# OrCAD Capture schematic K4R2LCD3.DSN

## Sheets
1 P3: Microtech 320x240 3.5": size Custom; title: K4 Microtech 3.5 adapter; rev: 1.0; note: K4R2-LCD
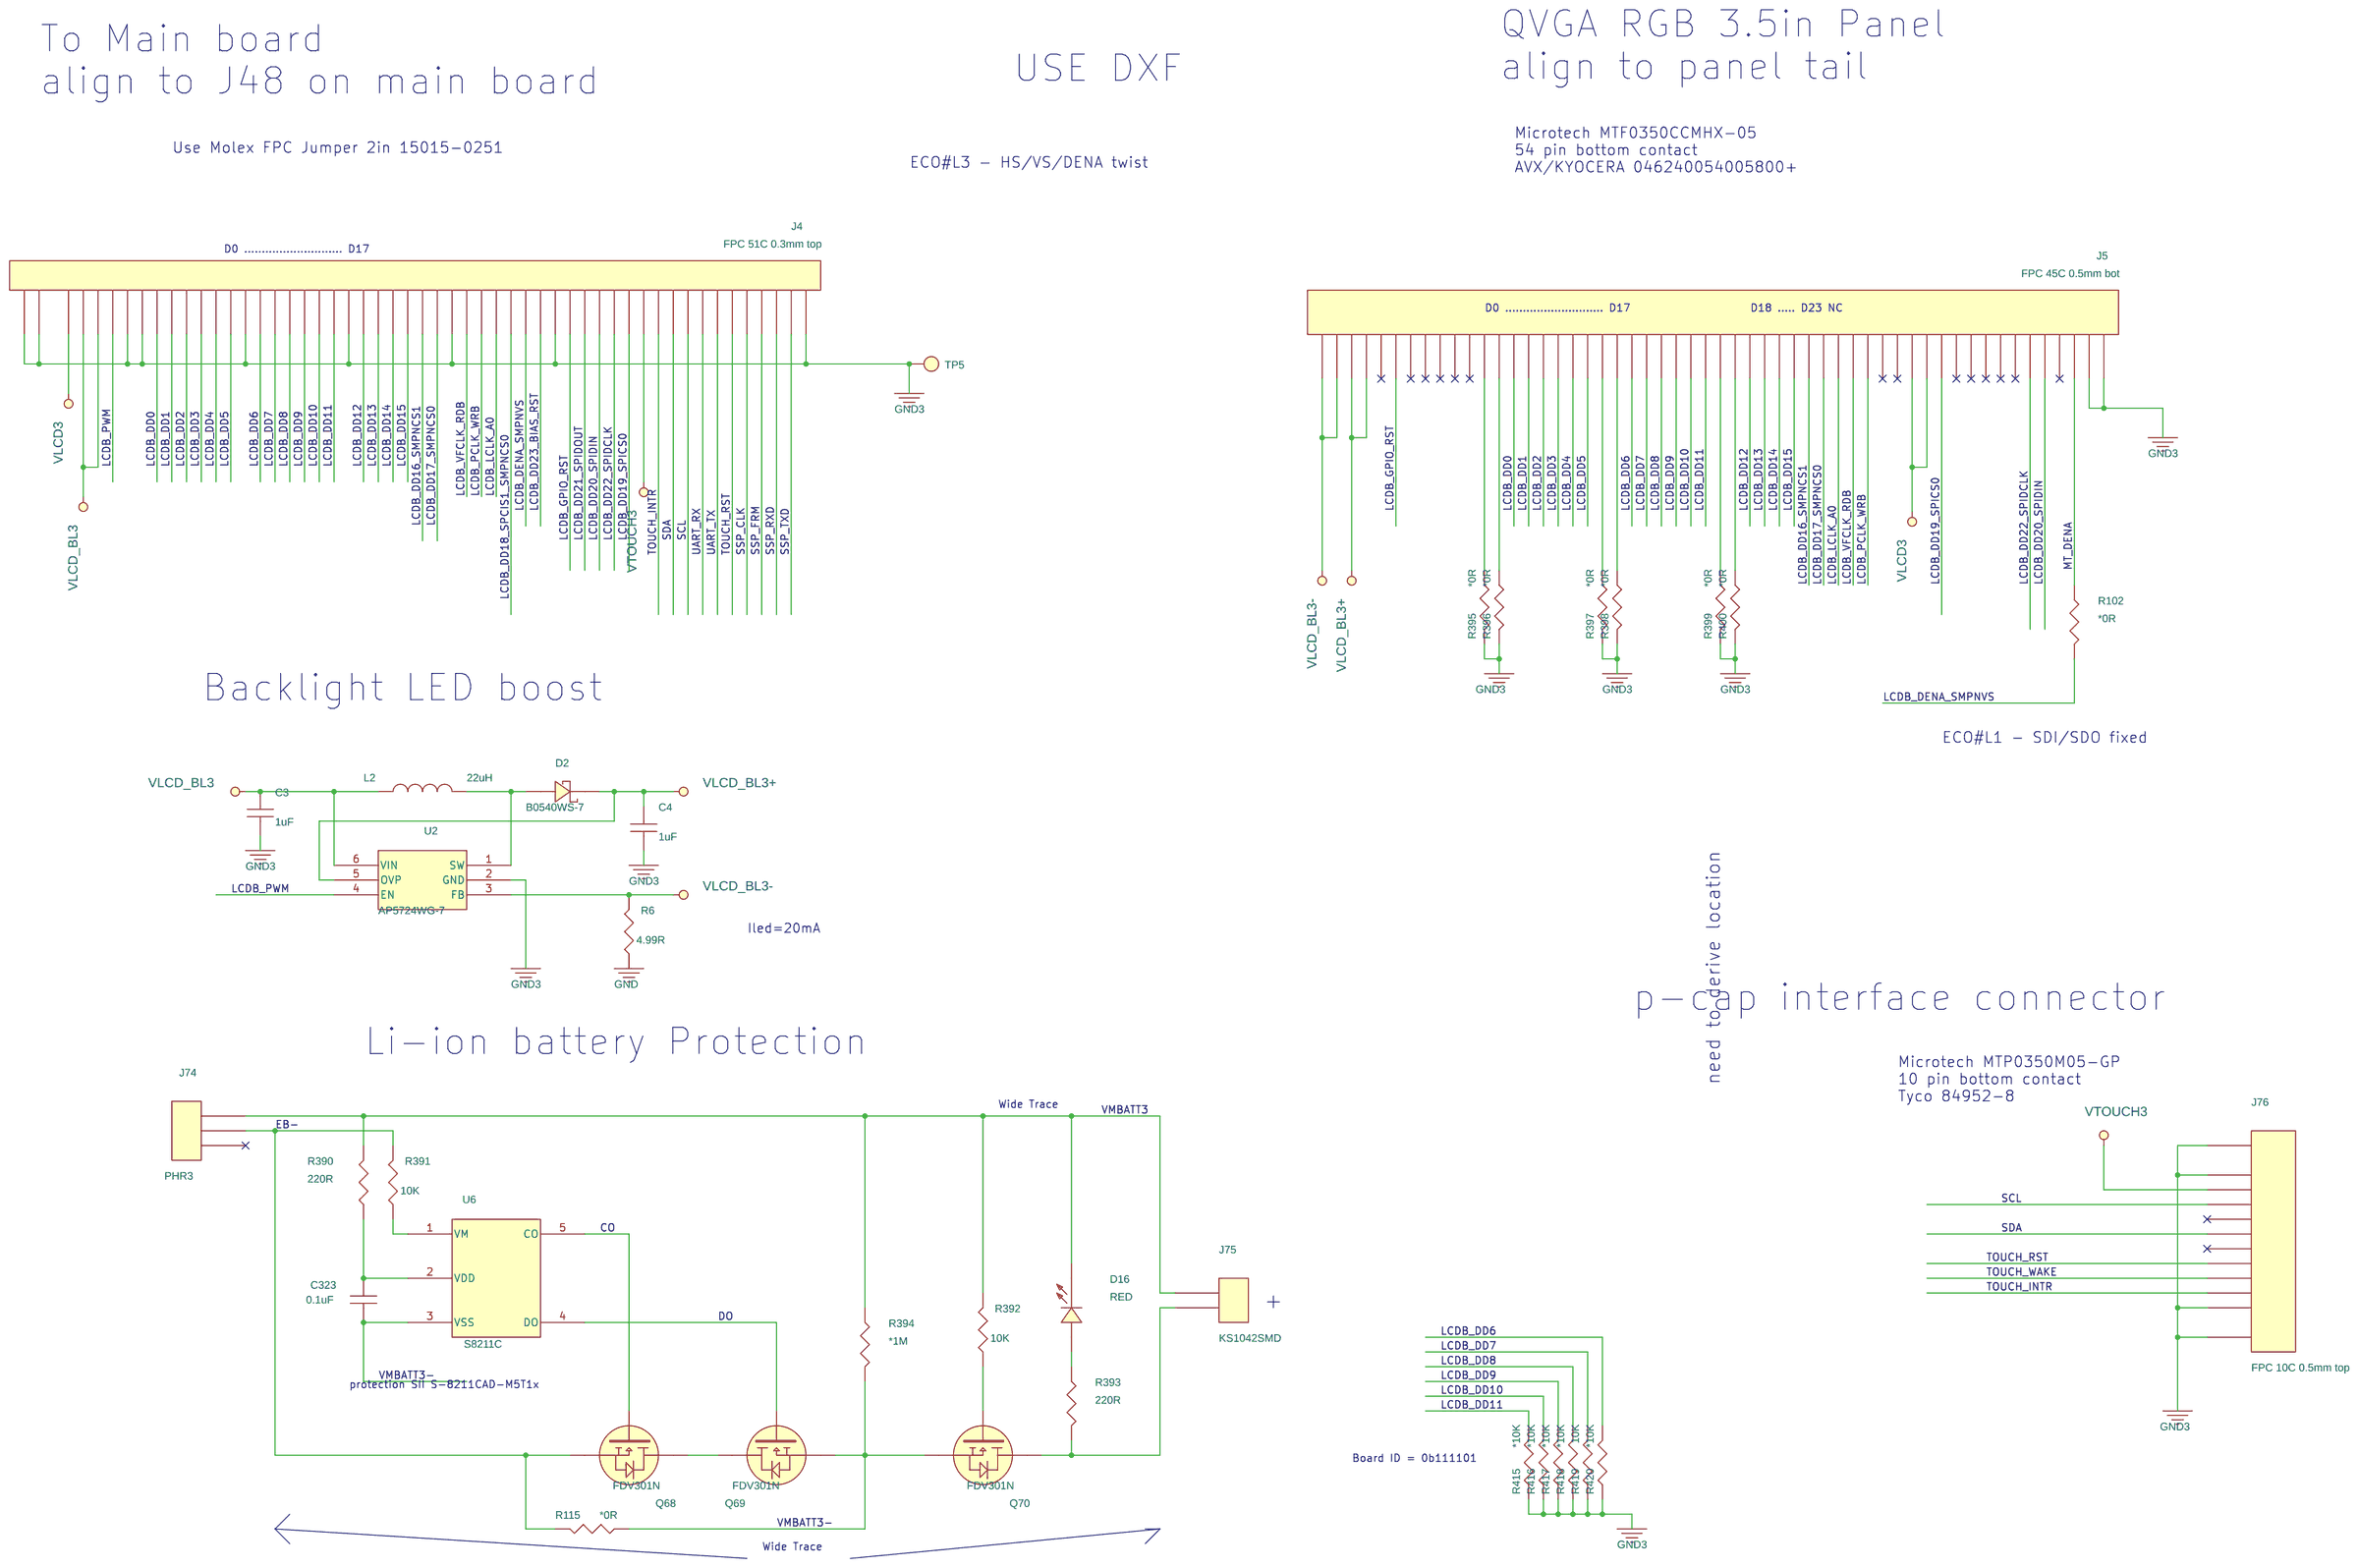
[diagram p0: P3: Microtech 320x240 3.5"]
2 P1: Title block: title: K4 LCD bridge
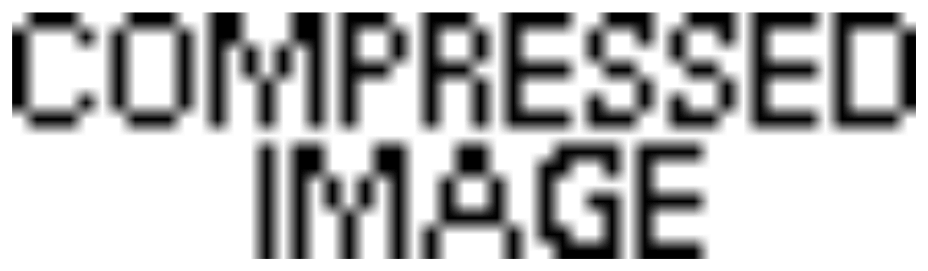
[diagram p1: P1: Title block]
3 P9: reconfigurable adapter: size Custom; title: K4 Configurable adapter
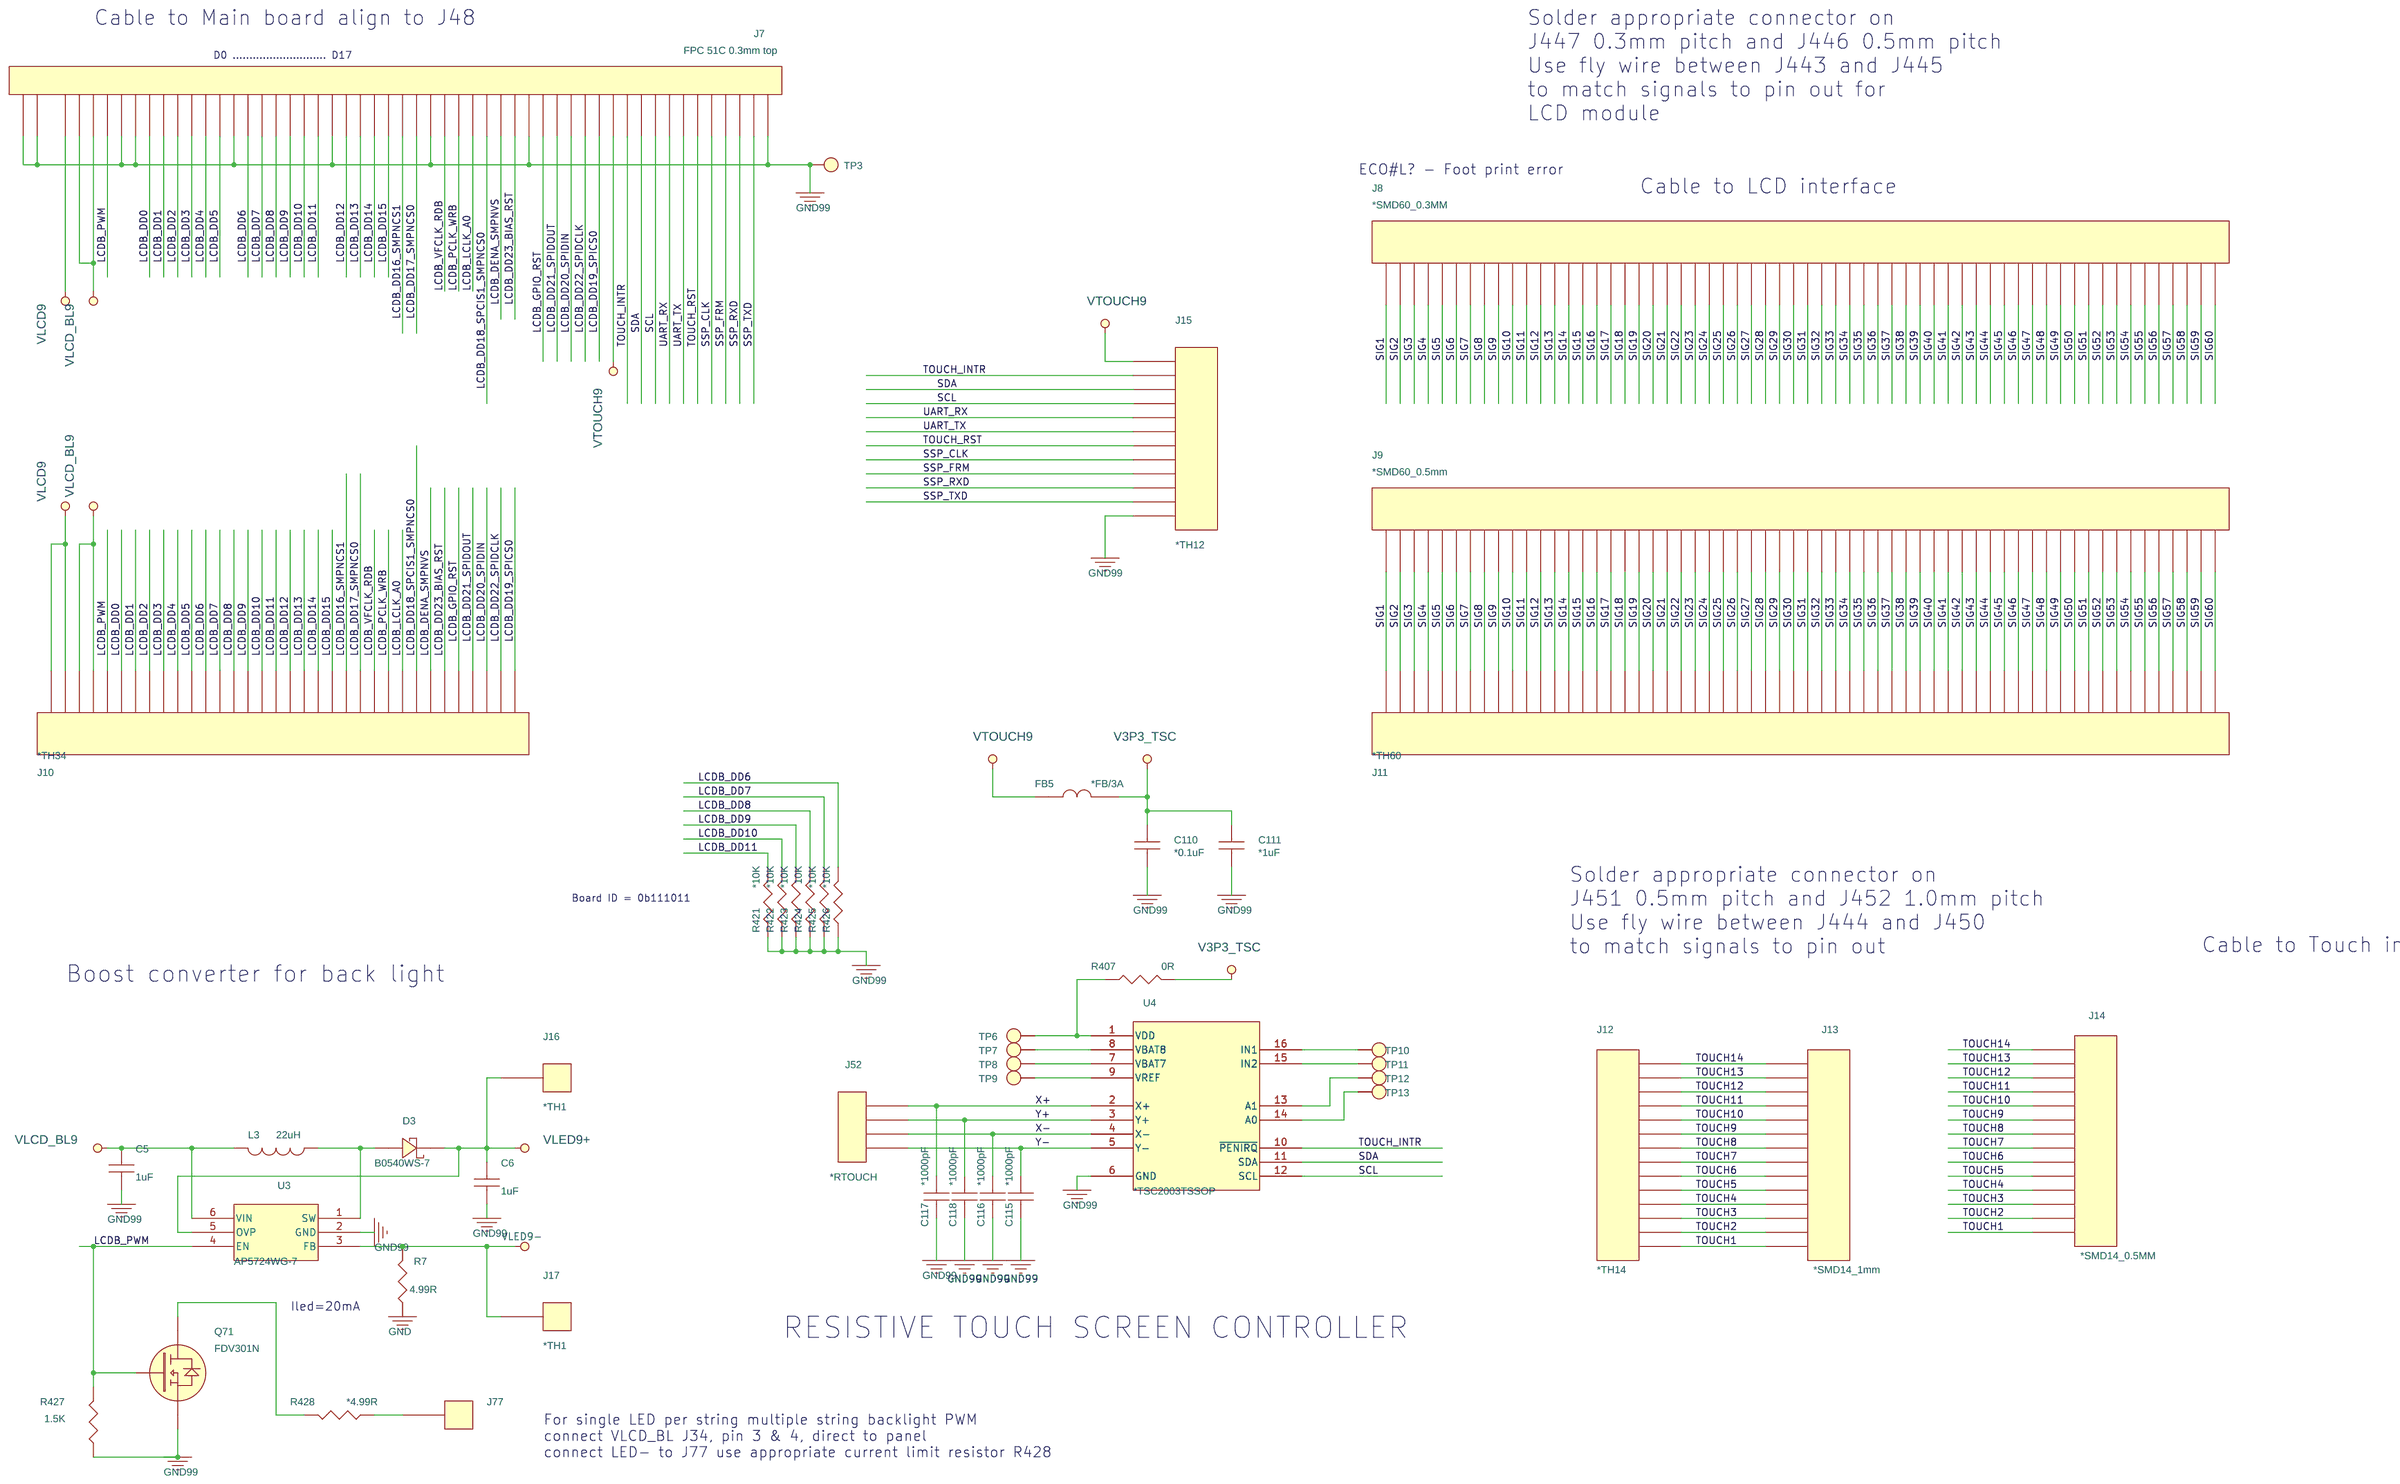
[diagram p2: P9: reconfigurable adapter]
4 P2: SmarterGlass 320x240 3.5": size Custom; title: K4 Smarterglass 3.5 adapter
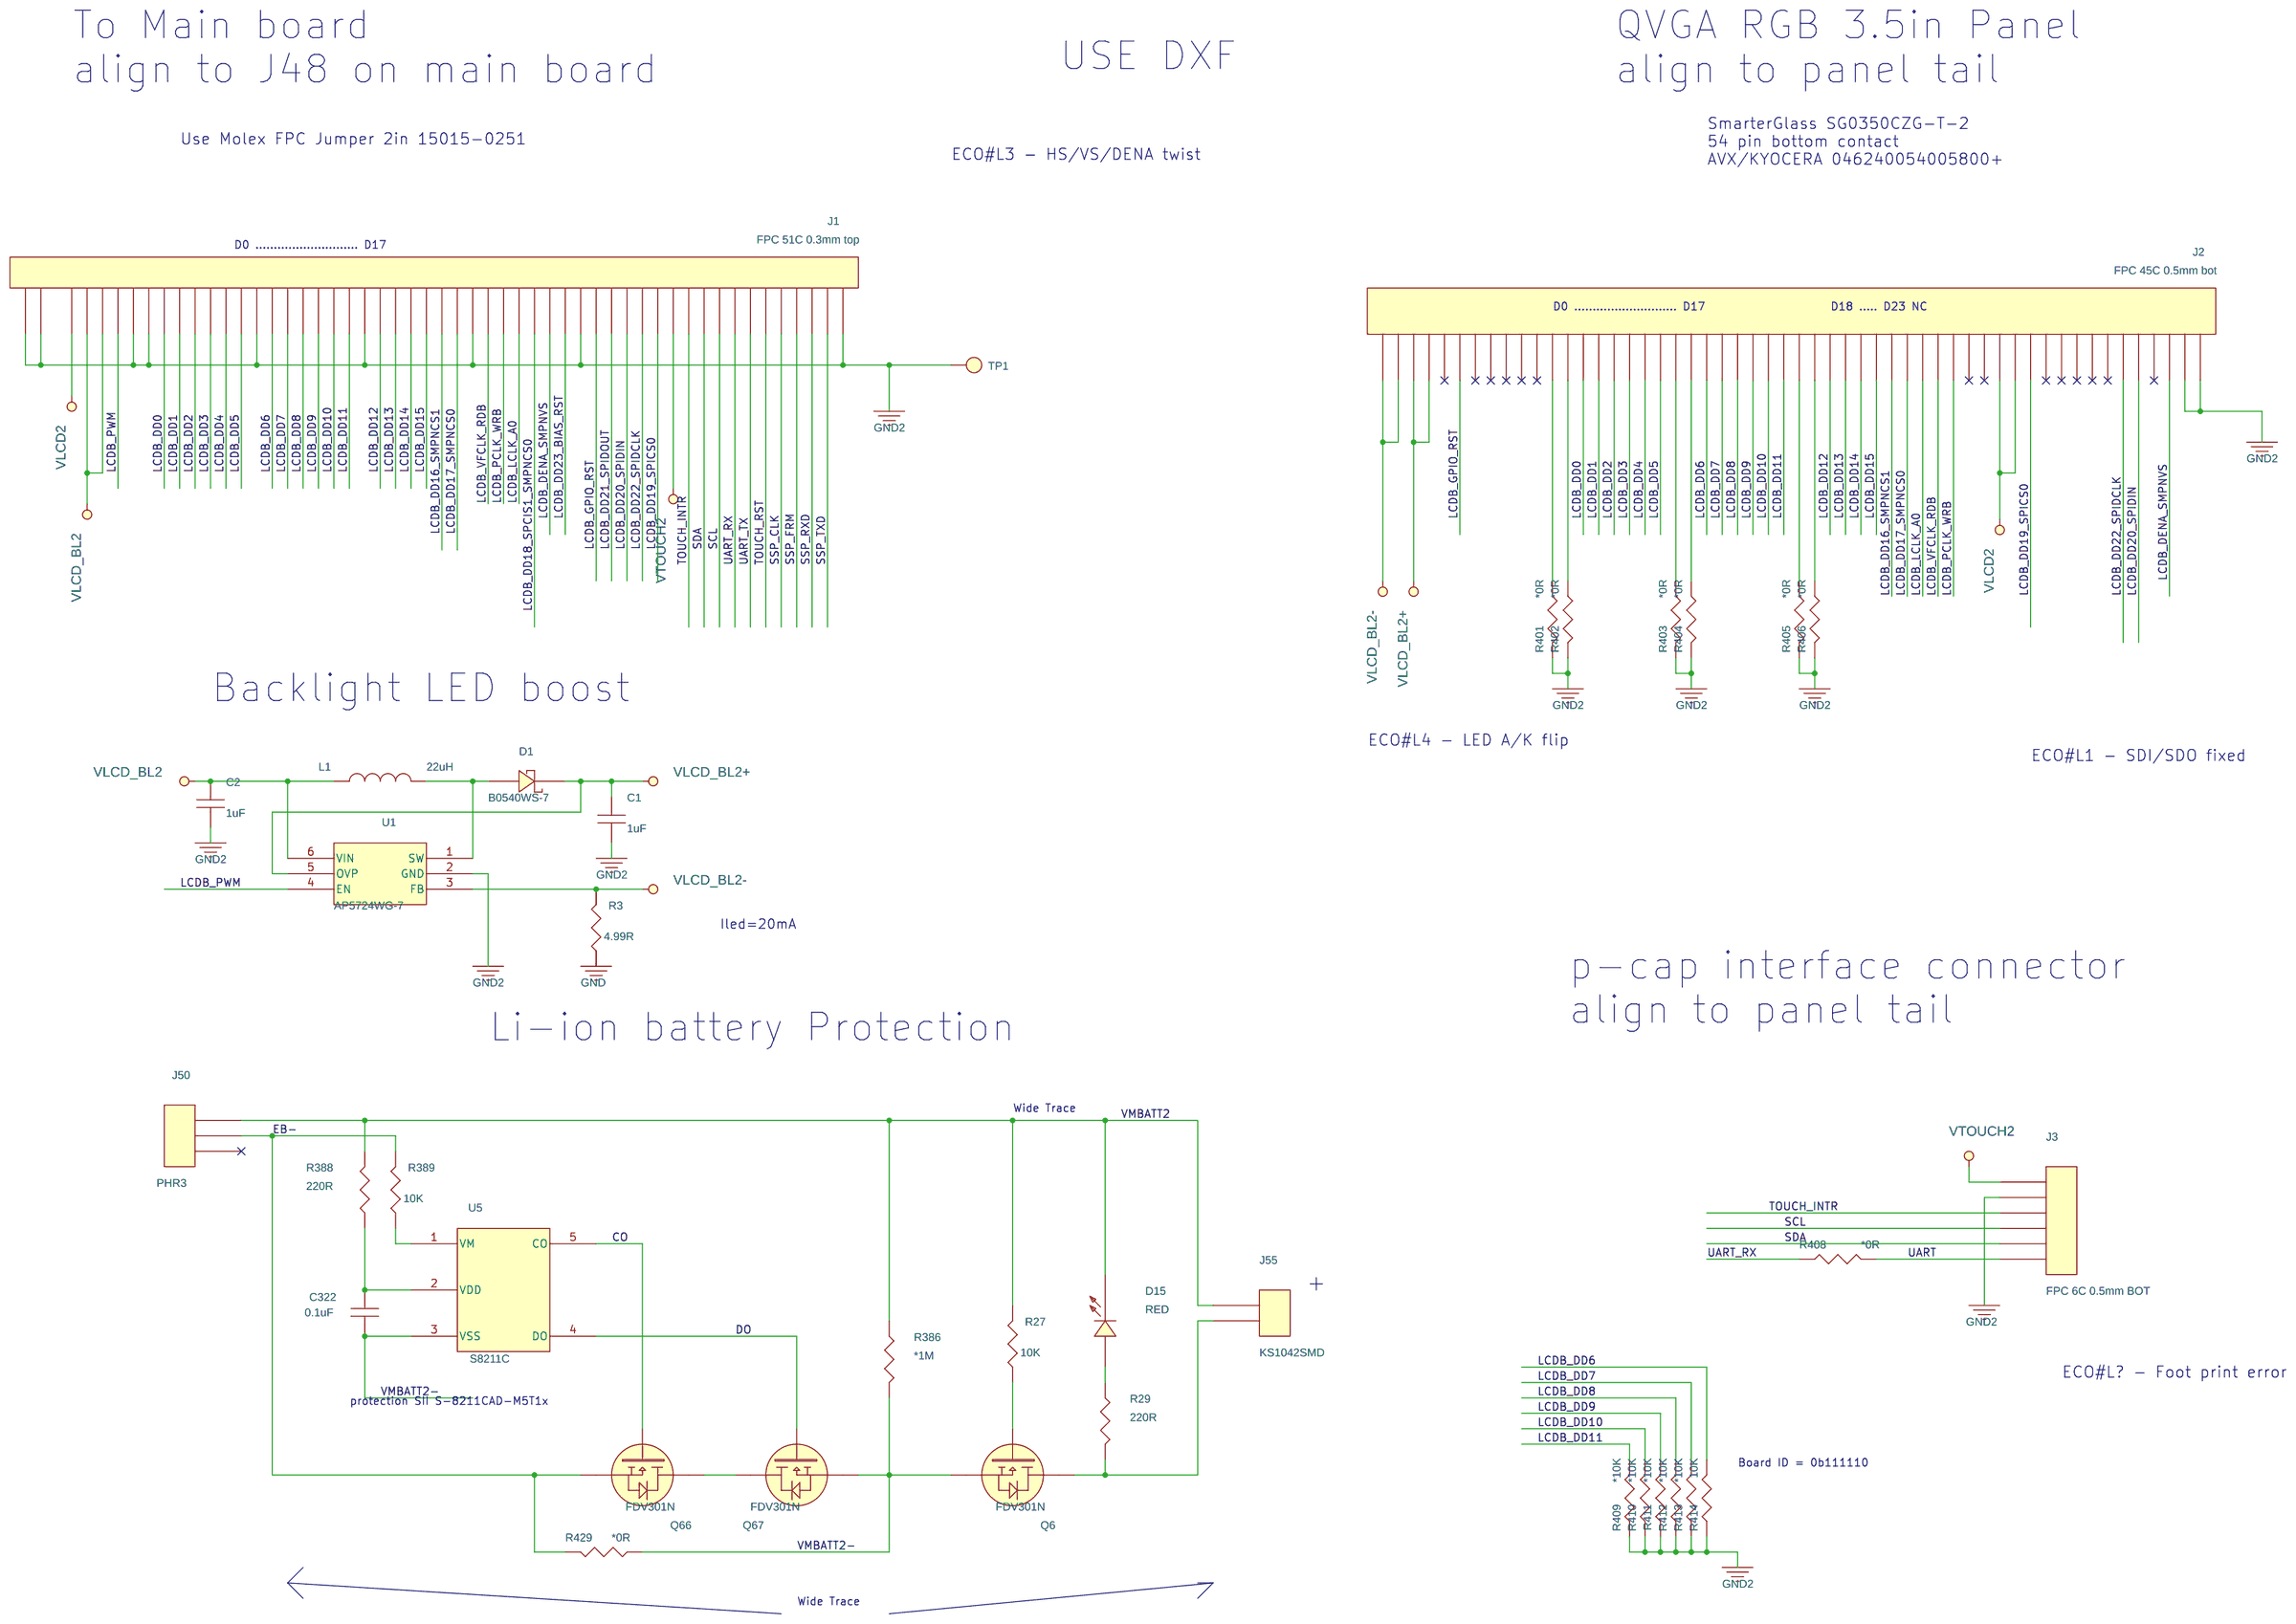
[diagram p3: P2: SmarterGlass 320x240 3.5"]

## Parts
sheet P2: SmarterGlass 320x240 3.5"
C1  1uF  [C0603]
C2  1uF  [C0603]
C322  0.1uF  [C-0402]
D1  B0540WS-7  [SOD-323]
D15  RED  [LED0603]
J1  FPC 51C 0.3mm top  [FH35_51_0_3MM]
J2  FPC 45C 0.5mm bot  [AVX6240-54]
J3  FPC 6C 0.5mm BOT  [SFV6R]
J50  PHR3  [JST_PHR3P_2mm]
J55  KS1042SMD  [KS1042SMD]
L1  22uH  [L-NR4012]
Q6  FDV301N  [SOT-23a]
Q66  FDV301N  [SOT-23a]
Q67  FDV301N  [SOT-23a]
R3  4.99R  [R-0402]
R27  10K  [R0402]
R29  220R  [R0402]
R386  *1M  [R0402]
R388  220R  [R0402]
R389  10K  [R0402]
R401  *0R  [R-0402]
R402  *0R  [R-0402]
R403  *0R  [R-0402]
R404  *0R  [R-0402]
R405  *0R  [R-0402]
R406  *0R  [R-0402]
R408  *0R  [R-0402]
R409  *10K  [R0402]
R410  *10K  [R0402]
R411  *10K  [R0402]
R412  *10K  [R0402]
R413  *10K  [R0402]
R414  10K  [R0402]
R429  *0R  [R-0603]
TP1  *T_POINT  [TP]
U1  AP5724WG-7  [SOT-23-6]
U5  S8211C  [sot23-5]
sheet P3: Microtech 320x240 3.5"
C3  1uF  [C0603]
C4  1uF  [C0603]
C323  0.1uF  [C-0402]
D2  B0540WS-7  [SOD-323]
D16  RED  [LED0603]
J4  FPC 51C 0.3mm top  [FH35_51_0_3MM]
J5  FPC 45C 0.5mm bot  [AVX6240-54]
J74  PHR3  [JST_PHR3P_2mm]
J75  KS1042SMD  [KS1042SMD]
J76  FPC 10C 0.5mm top  [SFV10]
L2  22uH  [L-NR4012]
Q68  FDV301N  [SOT-23a]
Q69  FDV301N  [SOT-23a]
Q70  FDV301N  [SOT-23a]
R6  4.99R  [R-0402]
R102  *0R  [R-0402]
R115  *0R  [R-0603]
R390  220R  [R0402]
R391  10K  [R0402]
R392  10K  [R0402]
R393  220R  [R0402]
R394  *1M  [R0402]
R395  *0R  [R-0402]
R396  *0R  [R-0402]
R397  *0R  [R-0402]
R398  *0R  [R-0402]
R399  *0R  [R-0402]
R400  *0R  [R-0402]
R415  *10K  [R0402]
R416  *10K  [R0402]
R417  *10K  [R0402]
R418  *10K  [R0402]
R419  10K  [R0402]
R420  *10K  [R0402]
TP5  *T_POINT  [TP]
U2  AP5724WG-7  [SOT-23-6]
U6  S8211C  [sot23-5]
sheet P9: reconfigurable adapter
C5  1uF  [C0603]
C6  1uF  [C0603]
C110  *0.1uF  [C-0402]
C111  *1uF  [C-0603]
C115  *1000pF  [C-0402]
C116  *1000pF  [C-0402]
C117  *1000pF  [C-0402]
C118  *1000pF  [C-0402]
D3  B0540WS-7  [SOD-323]
FB5  *FB/3A  [L-0603]
J7  FPC 51C 0.3mm top  [FH35_51_0_3MM]
J8  *SMD60_0.3MM  [SMD60_0_3MM]
J9  *SMD60_0.5mm  [SMD60_0_5mm]
J10  *TH34  [TH34_28MIL]
J11  *TH60  [TH60_28MIL]
J12  *TH14  [TH14_28MIL]
J13  *SMD14_1mm  [SMD14_1MM]
J14  *SMD14_0.5MM  [SMD14_50MIL]
J15  *TH12  [TH12_28MIL]
J16  *TH1  [TH1_28MM]
J17  *TH1  [TH1_28MM]
J52  *RTOUCH  [TH4_50MIL_28MM]
J77  *TH1  [TH1_28MM]
L3  22uH  [L-NR4012]
Q71  FDV301N  [SOT-23a]
R7  4.99R  [R-0402]
R407  0R  [R-0402]
R421  *10K  [R0402]
R422  *10K  [R0402]
R423  *10K  [R0402]
R424  10K  [R0402]
R425  *10K  [R0402]
R426  *10K  [R0402]
R427  1.5K  [R-0402]
R428  *4.99R  [R-0402]
TP3  *T_POINT  [TP]
TP6  *T_POINT  [TP]
TP7  *T_POINT  [TP]
TP8  *T_POINT  [TP]
TP9  *T_POINT  [TP]
TP10  *T_POINT  [TP]
TP11  *T_POINT  [TP]
TP12  *T_POINT  [TP]
TP13  *T_POINT  [TP]
U3  AP5724WG-7  [SOT-23-6]
U4  *TSC2003TSSOP  [TSSOP16]

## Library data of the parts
C1-C4 = CAP_NP: Desc: CAP CER 1UF 25V 10% X5R 0603; OPTION: TM035; Part Num: TMK107BJ105KA-T; Vendor: Taiyo
C322 C323 = CAP_NP: CAP CER .10UF 10V X5R 10% 0402; Desc: CAP CER .10UF 10V X7R 0402; Distributor: Digi-Key; Distributor Part Number: 445-1265-1-ND; Manufacturer: C1005X5R1A104K; Manufacturer Part Number: CAP CER .10UF 10V X5R 10% 0402; Part Num: C1005X7R1A104K; Vendor: TDK
D1 D2 = DIODE_SCHOTTKY21: DIODE SCHOTTKY 1A 40V SMA; Desc: DIODE SCHOTTKY 40V 0.5A SOD323; Manufacturer: Diodes Inc; OPTION: TM035; Vendor: Diodes
D15 D16 = LED_SINGLE: Desc: LED RED RECT CLEAR 0603; Part Num: LTST-C193KRKT-5A; Vendor: Lite-On
J1 J4 = CONN_FLEX_51: Desc: CONN FPC 51POS 0.3MM TOP SMD; OPTION: TM035; Part Num: FH35-51S-0.3SHW(50); Vendor: HIrose
J2 J5 = CONN_FLEX_54: Desc: CONN FPC ONE-TOUCH LCK .5MM 54; OPTION: TM035; Part Num: 046240054005800+; Vendor: AVX
J3 = CON6: Desc: CONN FPC/FFC 6POS BOT .5MM R/A SMD; OPTION: TM035; Part Num: SFV6R-1STE1HLF; vendor: FCI
J50 J74 = CON3: Desc: CONN HEADER PH SIDE 3POS 2MM SMD; Part Num: S3B-PH-SM4-TB(LF)(SN); Vendor: JST
J55 J75 = CON2: Desc: HOLDER BATTERY 1CELL 18650 SMD; Part Num: 1042; Vendor: Keystone
L1 L2 = INDUCTOR: Desc: INDUCTOR 22UH 20% SMD; OPTION: TM035; Part Num: NR4012T220M; Vendor: Taiyo
Q6 Q66-Q71 = NMOS3: Desc: MOSFET N-CH 25V 220MA SOT-23; Vendor: FAIRCHILD
R3 R6 = Res_0: Desc: RES 4.99 OHM 1/16W 1% 0402 SMD; OPTION: TM035; Part Num: CRCW04024R99FKED; Vendor: Vishay
R27 R389 R391 R392 R409-R426 = Res_0: Desc: RES 10K OHM 1/10W 5% 0402 SMD; Part Num: ERJ-2GEJ103X; Vendor: Panasonic
R29 R388 R390 R393 = Res_0: Desc: RES 220 OHM 1/10W 1% 0402 SMD; Part Num: ERJ-2RKF2200X; Vendor: Panasonic
R386 R394 = Res_0: Desc: RES 1M OHM 1/10W 5% 0402 SMD; Part Num: ERJ-2GEJ105X; Vendor: Panasonic
R395-R406 = Res_0: Desc: RES 0.0 OHM 1/10W 0402 SMD; Distributor: Digi-Key; Distributor PN: P15979CT-ND; Manufacturer: Panasonic Electronic Components; Manufacturer PN: ERJ-1GN0R00C; Mfr: Generic; OPTION: LIPO; Part Num: ERJ-2GE0R00X; Vendor: Panasonic; ccc: RES 0.0 OHM 1/10W 0402 SMD
R102 R407 R408 = Res_0: Desc: RES 0.0 OHM 1/10W 0402 SMD; Mfr: Generic; OPTION: LIPO; Part Num: ERJ-2GE0R00X; Vendor: Panasonic; ccc: RES 0.0 OHM 1/10W 0402 SMD
R115 R429 = R_0: Desc: RES 0.0 OHM 1/10W 0603 SMD; Mfr: Generic; Part Num: ERJ-3GEY0R00V; Vendor: Panasonic
TP1 TP3 TP5-TP13 = T_POINT: Desc: SMT Test Point; OPTION: TM035; Part Num: NA; Vendor: Test
U1 U2 = AP5724WG-7: Desc: IC LED DRVR WHITE BCKLGT SOT23-6; OPTION: TM035; Vendor: Diodes
U5 U6 = S8211C
J76 = FPC10-2mtg: Desc: CONN FPC/FFC 10POS .5MM R/A SMD; Distributor: Digi-Key; Distributor PN: 609-4306-2-ND; Manufacturer: FCI; Manufacturer PN: SFV10R-2STE1HLF; Part Num: SFV10R-2STE1HLF; Vendor: FCI
C5 C6 = CAP_NP: Desc: CAP CER 1UF 25V 10% X5R 0603; Part Num: TMK107BJ105KA-T; Vendor: Taiyo
C110 = CAP_NP_0: Desc: CAP CER .10UF 10V X7R 0402; Part Num: C1005X7R1A104K; Vendor: TDK
C111 = CAP_NP_0: Desc: CAP 1uF 10% 0603 10V X7R; Part Num: C1608X7R1A105K; Vendor: TDK
C115-C118 = CAP_NP_0: Desc: CAP 1nF 10% 0402 25V X7R; Part Num: C0402S102K3RACTU; Vendor: Kemet; mfg: Kemet; mfg_pn: C0402S102K3RACTU
D3 = DIODE_SCHOTTKY21: DIODE SCHOTTKY 1A 40V SMA; Desc: DIODE SCHOTTKY 40V 0.5A SOD323; Manufacturer: Diodes Inc; Vendor: Diodes
FB5 = FERRITE_BEAD_0: Desc: FERRITE CHIP 120 OHM 3000MA 0603; Part Num: BLM18KG121TN1; Vendor: Murata
J7 = CONN_FLEX_51: Desc: CONN FPC 51POS 0.3MM TOP SMD; Part Num: FH35-51S-0.3SHW(50); Vendor: HIrose
J8 J9 = CON60: Desc: PCB foot print; Part Num: N/A; Vendor: PCB fab
J10 = CON34: Desc: PCB foot print 2x17 x 28mil hole; Part Num: N/A; Vendor: PCB fab
J11 = CON60: Desc: PCB foot print 2x30 28mil hole; Part Num: N/A; Vendor: PCB fab
J12 = CON14: Desc: PCB foot print 1x14 x 28mil hole; Part Num: N/A; Vendor: PCB fab
J13 J14 = CON14: Desc: PCB foot print; Part Num: N/A; Vendor: PCB fab
J15 = CON12: Desc: PCB foot print 2x6 x 28mil hole; Part Num: N/A; Vendor: PCB fab
J16 J17 J77 = CON1: Desc: PCB foot print 28mil hole; Part Num: N/A; Vendor: PCB fab
J52 = CON4: Desc: PCB TH 100mil D28mm; Part Num: N/A
L3 = INDUCTOR: Desc: INDUCTOR 22UH 20% SMD; Part Num: NR4012T220M; Vendor: Taiyo
R7 R428 = Res_0: Desc: RES 4.99 OHM 1/16W 1% 0402 SMD; Part Num: CRCW04024R99FKED; Vendor: Vishay
R427 = Res_0: Desc: RES 1.5K OHM 1/10W 5% 0402 SMD; Part Num: ERJ-2GEJ152X; Vendor: Panasonic; ccc: RES 0.0 OHM 1/10W 0402 SMD
U3 = AP5724WG-7: Desc: IC LED DRVR WHITE BCKLGT SOT23-6; Vendor: Diodes
U4 = TSC2003

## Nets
GND2: C1.2 C2.2 J1.1 J1.18 J1.25 J1.32 J1.39 J1.46 J1.47 J1.M1 J1.M2 J2.53 J2.54 J3.2 R3.2 R401.1 R402.1 R403.1 R404.1 R405.1 R406.1 R409.2 R410.2 R411.2 R412.2 R413.2 R414.2 TP1.1(TP) U1.2(GND)
GND3: C3.2 C4.2 J4.1 J4.18 J4.25 J4.32 J4.39 J4.46 J4.47 J4.M1 J4.M2 J5.53 J5.54 J76.1 J76.10 J76.M1 J76.M2 R6.2 R395.1 R396.1 R397.1 R398.1 R399.1 R400.1 R415.2 R416.2 R417.2 R418.2 R419.2 R420.2 TP5.1(TP) U2.2(GND)
GND99: C5.2 C6.2 C110.2 C111.2 C115.2 C116.2 C117.2 C118.2 J7.1 J7.18 J7.25 J7.32 J7.39 J7.46 J7.47 J7.M1 J7.M2 J15.12 Q71.S R7.2 R421.2 R422.2 R423.2 R424.2 R425.2 R426.2 R427.1 TP3.1(TP) U3.2(GND) U4.6(GND)
V3P3_TSC: C110.1 C111.1 FB5.2 R407.1
CO: Q66.G U5.5(CO)
CO (page P3: Microtech 320x240 3.5"): Q68.G U6.5(CO)
DO: Q67.G U5.4(DO)
DO (page P3: Microtech 320x240 3.5"): Q69.G U6.4(DO)
EB-: J50.2 Q66.S R389.1 R429.1
EB- (page P3: Microtech 320x240 3.5"): J74.2 Q68.S R115.1 R391.1
LCDB_DD0: J1.45 J2.14
LCDB_DD0 (page P3: Microtech 320x240 3.5"): J4.45 J5.14
LCDB_DD0 (page P9: reconfigurable adapter): J7.45 J10.6
LCDB_DD1: J1.44 J2.15
LCDB_DD1 (page P3: Microtech 320x240 3.5"): J4.44 J5.15
LCDB_DD1 (page P9: reconfigurable adapter): J7.44 J10.7
LCDB_DD2: J1.43 J2.16
LCDB_DD2 (page P3: Microtech 320x240 3.5"): J4.43 J5.16
LCDB_DD2 (page P9: reconfigurable adapter): J7.43 J10.8
LCDB_DD3: J1.42 J2.17
LCDB_DD3 (page P3: Microtech 320x240 3.5"): J4.42 J5.17
LCDB_DD3 (page P9: reconfigurable adapter): J7.42 J10.9
LCDB_DD4: J1.41 J2.18
LCDB_DD4 (page P3: Microtech 320x240 3.5"): J4.41 J5.18
LCDB_DD4 (page P9: reconfigurable adapter): J7.41 J10.10
LCDB_DD5: J1.40 J2.19
LCDB_DD5 (page P3: Microtech 320x240 3.5"): J4.40 J5.19
LCDB_DD5 (page P9: reconfigurable adapter): J7.40 J10.11
LCDB_DD6: J1.38 J2.22 R414.1
LCDB_DD6 (page P3: Microtech 320x240 3.5"): J4.38 J5.22 R420.1
LCDB_DD6 (page P9: reconfigurable adapter): J7.38 J10.12 R426.1
LCDB_DD7: J1.37 J2.23 R413.1
LCDB_DD7 (page P3: Microtech 320x240 3.5"): J4.37 J5.23 R419.1
LCDB_DD7 (page P9: reconfigurable adapter): J7.37 J10.13 R425.1
LCDB_DD8: J1.36 J2.24 R412.1
LCDB_DD8 (page P3: Microtech 320x240 3.5"): J4.36 J5.24 R418.1
LCDB_DD8 (page P9: reconfigurable adapter): J7.36 J10.14 R424.1
LCDB_DD9: J1.35 J2.25 R411.1
LCDB_DD9 (page P3: Microtech 320x240 3.5"): J4.35 J5.25 R417.1
LCDB_DD9 (page P9: reconfigurable adapter): J7.35 J10.15 R423.1
LCDB_DD10: J1.34 J2.26 R410.1
LCDB_DD10 (page P3: Microtech 320x240 3.5"): J4.34 J5.26 R416.1
LCDB_DD10 (page P9: reconfigurable adapter): J7.34 J10.16 R422.1
LCDB_DD11: J1.33 J2.27 R409.1
LCDB_DD11 (page P3: Microtech 320x240 3.5"): J4.33 J5.27 R415.1
LCDB_DD11 (page P9: reconfigurable adapter): J7.33 J10.17 R421.1
LCDB_DD12: J1.31 J2.30
LCDB_DD12 (page P3: Microtech 320x240 3.5"): J4.31 J5.30
LCDB_DD12 (page P9: reconfigurable adapter): J7.31 J10.18
LCDB_DD13: J1.30 J2.31
LCDB_DD13 (page P3: Microtech 320x240 3.5"): J4.30 J5.31
LCDB_DD13 (page P9: reconfigurable adapter): J7.30 J10.19
LCDB_DD14: J1.29 J2.32
LCDB_DD14 (page P3: Microtech 320x240 3.5"): J4.29 J5.32
LCDB_DD14 (page P9: reconfigurable adapter): J7.29 J10.20
LCDB_DD15: J1.28 J2.33
LCDB_DD15 (page P3: Microtech 320x240 3.5"): J4.28 J5.33
LCDB_DD15 (page P9: reconfigurable adapter): J7.28 J10.21
LCDB_DD16_SMPNCS1: J1.27 J2.34
LCDB_DD16_SMPNCS1 (page P3: Microtech 320x240 3.5"): J4.27 J5.34
LCDB_DD16_SMPNCS1 (page P9: reconfigurable adapter): J7.27 J10.22
LCDB_DD17_SMPNCS0: J1.26 J2.35
LCDB_DD17_SMPNCS0 (page P3: Microtech 320x240 3.5"): J4.26 J5.35
LCDB_DD17_SMPNCS0 (page P9: reconfigurable adapter): J7.26 J10.23
LCDB_DD18_SPCIS1_SMPNCS0: J1.21
LCDB_DD18_SPCIS1_SMPNCS0 (page P3: Microtech 320x240 3.5"): J4.21
LCDB_DD18_SPCIS1_SMPNCS0 (page P9: reconfigurable adapter): J7.21 J10.27
LCDB_DD19_SPICS0: J1.13 J2.43
LCDB_DD19_SPICS0 (page P3: Microtech 320x240 3.5"): J4.13 J5.43
LCDB_DD19_SPICS0 (page P9: reconfigurable adapter): J7.13 J10.34
LCDB_DD20_SPIDIN: J1.15 J2.50
LCDB_DD20_SPIDIN (page P3: Microtech 320x240 3.5"): J4.15 J5.50
LCDB_DD20_SPIDIN (page P9: reconfigurable adapter): J7.15 J10.32
LCDB_DD21_SPIDOUT: J1.16
LCDB_DD21_SPIDOUT (page P3: Microtech 320x240 3.5"): J4.16
LCDB_DD21_SPIDOUT (page P9: reconfigurable adapter): J7.16 J10.31
LCDB_DD22_SPIDCLK: J1.14 J2.49
LCDB_DD22_SPIDCLK (page P3: Microtech 320x240 3.5"): J4.14 J5.49
LCDB_DD22_SPIDCLK (page P9: reconfigurable adapter): J7.14 J10.33
LCDB_DD23_BIAS_RST: J1.19
LCDB_DD23_BIAS_RST (page P3: Microtech 320x240 3.5"): J4.19
LCDB_DD23_BIAS_RST (page P9: reconfigurable adapter): J7.19 J10.29
LCDB_DENA_SMPNVS: J1.20 J2.52
LCDB_DENA_SMPNVS (page P3: Microtech 320x240 3.5"): J4.20 R102.1
LCDB_DENA_SMPNVS (page P9: reconfigurable adapter): J7.20 J10.28
LCDB_GPIO_RST: J1.17 J2.6
LCDB_GPIO_RST (page P3: Microtech 320x240 3.5"): J4.17 J5.6
LCDB_GPIO_RST (page P9: reconfigurable adapter): J7.17 J10.30
LCDB_LCLK_A0: J1.22 J2.36
LCDB_LCLK_A0 (page P3: Microtech 320x240 3.5"): J4.22 J5.36
LCDB_LCLK_A0 (page P9: reconfigurable adapter): J7.22 J10.26
LCDB_PCLK_WRB: J1.23 J2.38
LCDB_PCLK_WRB (page P3: Microtech 320x240 3.5"): J4.23 J5.38
LCDB_PCLK_WRB (page P9: reconfigurable adapter): J7.23 J10.25
LCDB_PWM: J1.48 U1.4(EN)
LCDB_PWM (page P3: Microtech 320x240 3.5"): J4.48 U2.4(EN)
LCDB_PWM (page P9: reconfigurable adapter): J7.48 J10.5 Q71.G R427.2 U3.4(EN)
LCDB_VFCLK_RDB: J1.24 J2.37
LCDB_VFCLK_RDB (page P3: Microtech 320x240 3.5"): J4.24 J5.37
LCDB_VFCLK_RDB (page P9: reconfigurable adapter): J7.24 J10.24
MT_DENA: J5.52 R102.2
SCL: J1.9 J3.4
SCL (page P3: Microtech 320x240 3.5"): J4.9 J76.3
SCL (page P9: reconfigurable adapter): J7.9 J15.4 U4.12(SCL)
SDA: J1.10 J3.5
SDA (page P3: Microtech 320x240 3.5"): J4.10 J76.5
SDA (page P9: reconfigurable adapter): J7.10 J15.3 U4.11(SDA)
SIG1: J8.1 J9.1 J11.1
SIG2: J8.2 J9.2 J11.2
SIG3: J8.3 J9.3 J11.3
SIG4: J8.4 J9.4 J11.4
SIG5: J8.5 J9.5 J11.5
SIG6: J8.6 J9.6 J11.6
SIG7: J8.7 J9.7 J11.7
SIG8: J8.8 J9.8 J11.8
SIG9: J8.9 J9.9 J11.9
SIG10: J8.10 J9.10 J11.10
SIG11: J8.11 J9.11 J11.11
SIG12: J8.12 J9.12 J11.12
SIG13: J8.13 J9.13 J11.13
SIG14: J8.14 J9.14 J11.14
SIG15: J8.15 J9.15 J11.15
SIG16: J8.16 J9.16 J11.16
SIG17: J8.17 J9.17 J11.17
SIG18: J8.18 J9.18 J11.18
SIG19: J8.19 J9.19 J11.19
SIG20: J8.20 J9.20 J11.20
SIG21: J8.21 J9.21 J11.21
SIG22: J8.22 J9.22 J11.22
SIG23: J8.23 J9.23 J11.23
SIG24: J8.24 J9.24 J11.24
SIG25: J8.25 J9.25 J11.25
SIG26: J8.26 J9.26 J11.26
SIG27: J8.27 J9.27 J11.27
SIG28: J8.28 J9.28 J11.28
SIG29: J8.29 J9.29 J11.29
SIG30: J8.30 J9.30 J11.30
SIG31: J8.31 J9.31 J11.31
SIG32: J8.32 J9.32 J11.32
SIG33: J8.33 J9.33 J11.33
SIG34: J8.34 J9.34 J11.34
SIG35: J8.35 J9.35 J11.35
SIG36: J8.36 J9.36 J11.36
SIG37: J8.37 J9.37 J11.37
SIG38: J8.38 J9.38 J11.38
SIG39: J8.39 J9.39 J11.39
SIG40: J8.40 J9.40 J11.40
SIG41: J8.41 J9.41 J11.41
SIG42: J8.42 J9.42 J11.42
SIG43: J8.43 J9.43 J11.43
SIG44: J8.44 J9.44 J11.44
SIG45: J8.45 J9.45 J11.45
SIG46: J8.46 J9.46 J11.46
SIG47: J8.47 J9.47 J11.47
SIG48: J8.48 J9.48 J11.48
SIG49: J8.49 J9.49 J11.49
SIG50: J8.50 J9.50 J11.50
SIG51: J8.51 J9.51 J11.51
SIG52: J8.52 J9.52 J11.52
SIG53: J8.53 J9.53 J11.53
SIG54: J8.54 J9.54 J11.54
SIG55: J8.55 J9.55 J11.55
SIG56: J8.56 J9.56 J11.56
SIG57: J8.57 J9.57 J11.57
SIG58: J8.58 J9.58 J11.58
SIG59: J8.59 J9.59 J11.59
SIG60: J8.60 J9.60 J11.60
SSP_CLK: J1.5
SSP_CLK (page P3: Microtech 320x240 3.5"): J4.5
SSP_CLK (page P9: reconfigurable adapter): J7.5 J15.8
SSP_FRM: J1.4
SSP_FRM (page P3: Microtech 320x240 3.5"): J4.4
SSP_FRM (page P9: reconfigurable adapter): J7.4 J15.9
SSP_RXD: J1.3
SSP_RXD (page P3: Microtech 320x240 3.5"): J4.3
SSP_RXD (page P9: reconfigurable adapter): J7.3 J15.10
SSP_TXD: J1.2
SSP_TXD (page P3: Microtech 320x240 3.5"): J4.2
SSP_TXD (page P9: reconfigurable adapter): J7.2 J15.11
TOUCH1: J12.1 J13.1 J14.1
TOUCH2: J12.2 J13.2 J14.2
TOUCH3: J12.3 J13.3 J14.3
TOUCH4: J12.4 J13.4 J14.4
TOUCH5: J12.5 J13.5 J14.5
TOUCH6: J12.6 J13.6 J14.6
TOUCH7: J12.7 J13.7 J14.7
TOUCH8: J12.8 J13.8 J14.8
TOUCH9: J12.9 J13.9 J14.9
TOUCH10: J12.10 J13.10 J14.10
TOUCH11: J12.11 J13.11 J14.11
TOUCH12: J12.12 J13.12 J14.12
TOUCH13: J12.13 J13.13 J14.13
TOUCH14: J12.14 J13.14 J14.14
TOUCH_INTR: J1.11 J3.3
TOUCH_INTR (page P3: Microtech 320x240 3.5"): J4.11 J76.9
TOUCH_INTR (page P9: reconfigurable adapter): J7.11 J15.2 U4.10(~{PENIRQ})
TOUCH_RST: J1.6
TOUCH_RST (page P3: Microtech 320x240 3.5"): J4.6 J76.7
TOUCH_RST (page P9: reconfigurable adapter): J7.6 J15.7
TOUCH_WAKE: J76.8
UART: J3.6 R408.1
UART_RX: J1.8 R408.2
UART_RX (page P3: Microtech 320x240 3.5"): J4.8
UART_RX (page P9: reconfigurable adapter): J7.8 J15.5
UART_TX: J1.7
UART_TX (page P3: Microtech 320x240 3.5"): J4.7
UART_TX (page P9: reconfigurable adapter): J7.7 J15.6
VLCD2: J1.51 J2.41 J2.42
VLCD3: J4.51 J5.41 J5.42
VLCD9: J7.51 J10.1 J10.2
VLCD_BL2: C2.1 J1.49 J1.50 L1.1 U1.6(VIN)
VLCD_BL2+: C1.1 D1.1(K) J2.3 J2.4 U1.5(OVP)
VLCD_BL2-: J2.1 J2.2 R3.1 U1.3(FB)
VLCD_BL3: C3.1 J4.49 J4.50 L2.1 U2.6(VIN)
VLCD_BL3+: C4.1 D2.1(K) J5.3 J5.4 U2.5(OVP)
VLCD_BL3-: J5.1 J5.2 R6.1 U2.3(FB)
VLCD_BL9: C5.1 J7.49 J7.50 J10.3 J10.4 L3.1 U3.6(VIN)
VLED9+: C6.1 D3.1(K) J16.1 U3.5(OVP)
VLED9-: J17.1 R7.1 U3.3(FB)
VMBATT2: D15.2(CATHODE) J50.1 J55.1 R27.1 R386.2 R388.2
VMBATT2-: C322.2 Q6.S Q67.S R386.1 R429.2 U5.3(VSS)
VMBATT3: D16.2(CATHODE) J74.1 J75.1 R390.2 R392.1 R394.2
VMBATT3-: C323.2 Q69.S Q70.S R115.2 R394.1 U6.3(VSS)
VTOUCH2: J1.12 J3.1
VTOUCH3: J4.12 J76.2
VTOUCH9: FB5.1 J7.12 J15.1
X+: C117.1 J52.1 U4.2(X+)
X-: C116.1 J52.3 U4.4(X-)
Y+: C118.1 J52.2 U4.3(Y+)
Y-: C115.1 J52.4 U4.5(Y-)
N09983: D3.2(A) L3.2 U3.1(SW)
N26297: D1.2(A) L1.2 U1.1(SW)
N111357: D2.2(A) L2.2 U2.1(SW)
N143594: TP12.1(TP) U4.13(A1)
N143610: TP13.1(TP) U4.14(A0)
N145352: R407.2 TP6.1(TP) U4.1(VDD)
N145441: TP11.1(TP) U4.15(IN2)
N145445: TP10.1(TP) U4.16(IN1)
N145483: TP9.1(TP) U4.9(VREF)
N145487: TP8.1(TP) U4.7(VBAT7)
N145491: TP7.1(TP) U4.8(VBAT8)
N174420: J55.2 Q6.D R29.1
N174867: Q6.G R27.2
N175073: D15.1(ANODE) R29.2
N211484: C322.1 R388.1 U5.2(VDD)
N211666: R389.2 U5.1(VM)
N211689: Q66.D Q67.D
N228967: C323.1 R390.1 U6.2(VDD)
N229053: R391.2 U6.1(VM)
N229081: Q68.D Q69.D
N229207: J75.2 Q70.D R393.1
N229239: Q70.G R392.2
N229297: D16.1(ANODE) R393.2
N236506: J5.12 R395.2
N236510: J5.13 R396.2
N236627: J5.20 R397.2
N236631: J5.21 R398.2
N236761: J5.28 R399.2
N236765: J5.29 R400.2
N237019: J2.12 R401.2
N237023: J2.13 R402.2
N237079: J2.20 R403.2
N237083: J2.21 R404.2
N237135: J2.28 R405.2
N237139: J2.29 R406.2
N251497: Q71.D R428.1
N251729: J77.1 R428.2

Not connected (* = marked no-connect by the designer): J2 5* 7* 8* 9* 10* 11* 39* 40* 44* 45* 46* 47* 48* 51*; J5 5* 7* 8* 9* 10* 11* 39* 40* 44* 45* 46* 47* 48* 51*; J50 3*; J74 3*; J76 4* 6*

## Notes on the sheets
sheet 1
- QVGA RGB 3.5in Panel
  align to panel tail
- To Main board
  align to J48 on main board
- USE DXF
- Microtech MTF0350CCMHX-05
  54 pin bottom contact
  AVX/KYOCERA 046240054005800+
- Use Molex FPC Jumper 2in 15015-0251
- ECO#L3 - HS/VS/DENA twist
- D0 ............................ D17
- D0 ............................ D17
- D18 ..... D23 NC
- Backlight LED boost
- ECO#L1 - SDI/SDO fixed
- Iled=20mA
- p-cap interface connector
- Li-ion battery Protection
- Microtech MTP0350M05-GP
  10 pin bottom contact
  Tyco 84952-8
- need to derive location
- Wide Trace
- +
- protection SII S-8211CAD-M5T1x
- Board ID = 0b111101
- Wide Trace
sheet 3
- Cable to Main board align to J48
- Solder appropriate connector on
  J447 0.3mm pitch and J446 0.5mm pitch
  Use fly wire between J443 and J445
  to match signals to pin out for
  LCD module
- D0 ............................ D17
- ECO#L? - Foot print error
- Cable to LCD interface
- Solder appropriate connector on
  J451 0.5mm pitch and J452 1.0mm pitch
  Use fly wire between J444 and J450
  to match signals to pin out
- Board ID = 0b111011
- Cable to Touch interface
- Boost converter for back light
- Iled=20mA
- RESISTIVE TOUCH SCREEN CONTROLLER
- For single LED per string multiple string backlight PWM
  connect VLCD_BL J34, pin 3 & 4, direct to panel
  connect LED- to J77 use appropriate current limit resistor R428
sheet 4
- To Main board
  align to J48 on main board
- QVGA RGB 3.5in Panel
  align to panel tail
- USE DXF
- SmarterGlass SG0350CZG-T-2
  54 pin bottom contact
  AVX/KYOCERA 046240054005800+
- Use Molex FPC Jumper 2in 15015-0251
- ECO#L3 - HS/VS/DENA twist
- D0 ............................ D17
- D0 ............................ D17
- D18 ..... D23 NC
- Backlight LED boost
- ECO#L4 - LED A/K flip
- ECO#L1 - SDI/SDO fixed
- Iled=20mA
- p-cap interface connector
  align to panel tail
- Li-ion battery Protection
- Wide Trace
- +
- ECO#L? - Foot print error
- protection SII S-8211CAD-M5T1x
- Board ID = 0b111110
- Wide Trace
